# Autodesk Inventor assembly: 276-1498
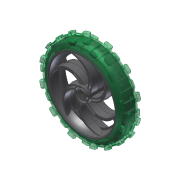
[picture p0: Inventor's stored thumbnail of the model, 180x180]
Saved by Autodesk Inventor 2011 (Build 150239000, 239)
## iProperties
Company: Autodesk Inc.
Created: 2010-06
Part Number: 276-1498
Document SubType Name: Assembly
Designer: Autodesk Inc.
Catalog Web Link: http://www.vexrobotics.com/products/accessories/motion/276-1498.html
Description: VEX 5" diameter Wheel. This wheel includes a knobby tire which works great on rough terrain or loose surfaces.
Vendor: Innovation First, Inc.
Author: Autodesk Inc.
Title: VEX Robotics Kit of Parts
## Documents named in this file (3)
- D:\@VEX\BZ-Parts Kit\Motion\Large Wheel.iam
- D:\@VEX\BZ-Parts Kit\Motion\Large Wheel Hub.ipt
- D:\@VEX\BZ-Parts Kit\Motion\Large Wheel Tire.ipt
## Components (2 placed, 2 different names)
1. Large Wheel Hub:1 — Mate:1, Mate:2, Mate:3
2. Large Wheel Tire:1 — Mate:1, Mate:2, Mate:3
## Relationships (3: Mate 3)
- Mate:1: Large Wheel Hub:1 ↔ Large Wheel Tire:1
- Mate:2: Large Wheel Hub:1 ↔ Large Wheel Tire:1
- Mate:3: Large Wheel Hub:1 ↔ Large Wheel Tire:1
